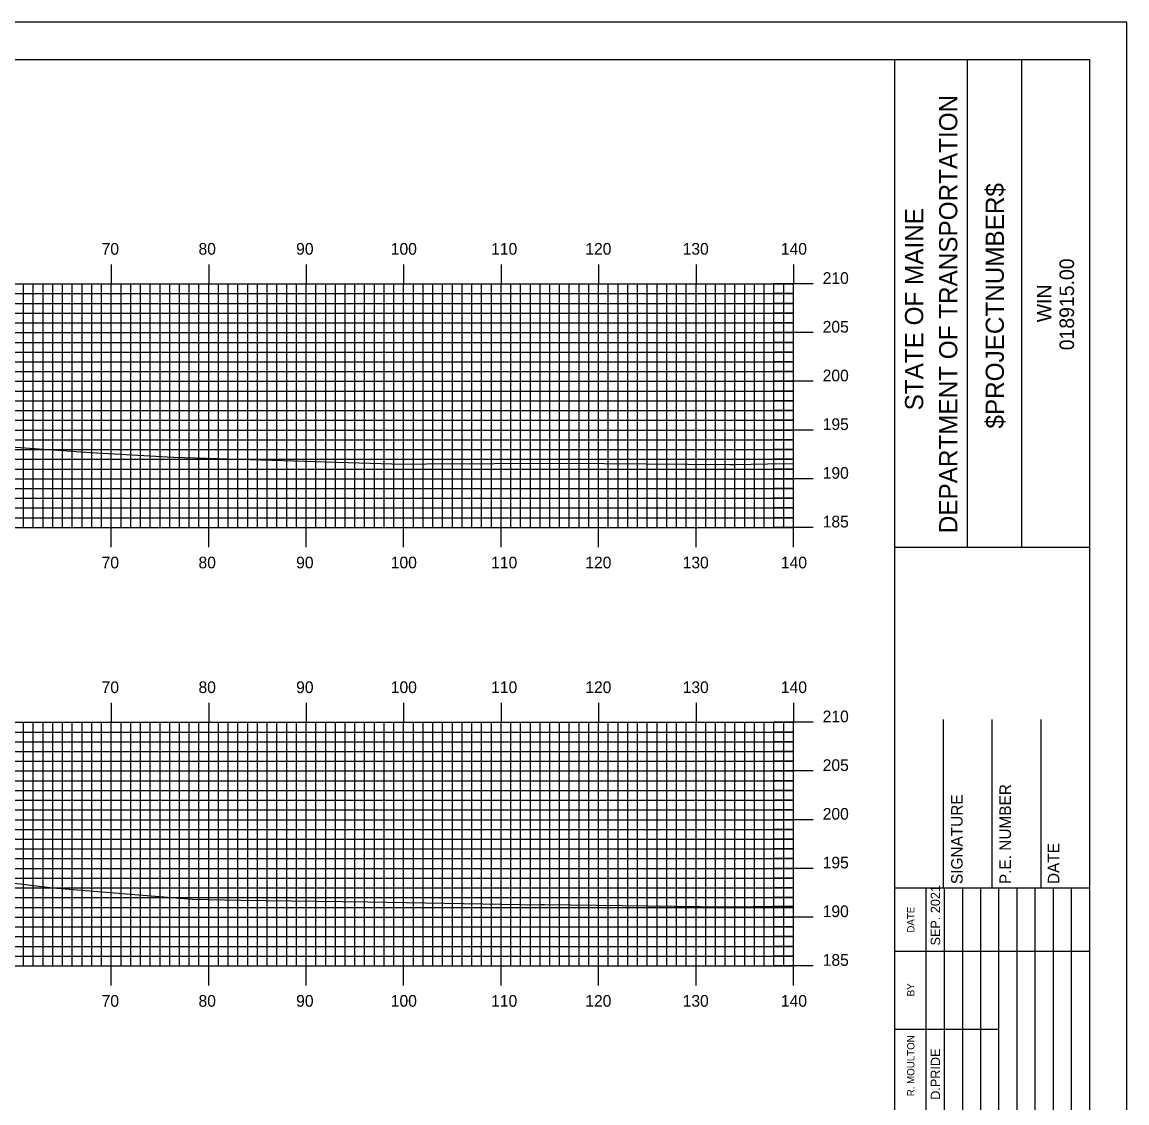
# Model space of a CAD drawing. Extents: x 1813735 to 1814078, y 442591 to 442811.
# Drawn here: x 1813961.3 to 1814074.7, y 442699.6 to 442810.5 of the extents above; entities that cross this region are included whole.
import ezdxf

# ---------------------------------------------------------------- set-up
doc = ezdxf.new("R2010")
doc.units = 0
for name, color, linetype in [('BORDER', 7, 'Continuous'), ('H_V ANNOTATION', 7, 'Continuous'), ('MAJOR', 7, 'Continuous'), ('MINOR', 7, 'Continuous'), ('PLOT BOUNDARY', 7, 'Continuous'), ('S_Roadway_Centerline', 7, 'Continuous')]:
    doc.layers.add(name, color=color, linetype=linetype)

msp = doc.modelspace()

# ---------------------------------------------------------------- linework, layer by layer
at = {"layer": 'BORDER'}
for p, q in [((1814050.88, 442596.67), (1814050.88, 442806.67)), ((1814058.34, 442756.66), (1814058.34, 442806.66)), ((1814063.93, 442756.66), (1814063.93, 442806.66)), ((1814050.88, 442756.65), (1814070.88, 442756.65)), ((1814055.88, 442721.67), (1814055.88, 442738.97)), ((1814060.88, 442721.67), (1814060.88, 442738.97)), ((1814065.88, 442721.67), (1814065.88, 442738.97)), ((1814050.88, 442721.67), (1814070.88, 442721.67))]:
    msp.add_line(p, q, dxfattribs=at)
msp.add_lwpolyline([(1813750.88, 442596.67), (1814070.88, 442596.67), (1814070.88, 442806.67), (1813750.88, 442806.67)], close=True, dxfattribs=at)
for points in [[(1814054.11, 442715.17), (1814054.11, 442721.67)], [(1814055.98, 442686.68), (1814055.98, 442721.67)], [(1814057.84, 442721.67), (1814057.84, 442686.68)], [(1814059.7, 442686.68), (1814059.7, 442721.67)], [(1814061.57, 442686.68), (1814061.57, 442721.67)], [(1814063.43, 442686.68), (1814063.43, 442721.67)], [(1814065.29, 442686.68), (1814065.29, 442721.67)], [(1814067.16, 442686.68), (1814067.16, 442721.67)], [(1814069.02, 442686.68), (1814069.02, 442721.67)], [(1814054.11, 442686.68), (1814054.11, 442720.26)], [(1814050.88, 442715.17), (1814070.88, 442715.17)], [(1814050.88, 442707.17), (1814054.11, 442707.17)], [(1814054.11, 442707.17), (1814061.56, 442707.17)]]:
    msp.add_lwpolyline(points, dxfattribs=at)
at = {"layer": 'MAJOR'}
for p, q in [((1813970.48, 442785.67), (1813970.48, 442783.67)), ((1813980.48, 442785.67), (1813980.48, 442783.67)), ((1813990.48, 442785.67), (1813990.48, 442783.67)), ((1814000.48, 442785.67), (1814000.48, 442783.67)), ((1814010.48, 442785.67), (1814010.48, 442783.67)), ((1814020.48, 442785.67), (1814020.48, 442783.67)), ((1814030.48, 442785.67), (1814030.48, 442783.67)), ((1814040.48, 442785.67), (1814040.48, 442783.67)), ((1813760.48, 442783.67), (1814040.48, 442783.67)), ((1813760.48, 442783.67), (1814040.48, 442783.67)), ((1813970.48, 442758.67), (1813970.48, 442783.67)), ((1813980.48, 442758.67), (1813980.48, 442783.67)), ((1813990.48, 442758.67), (1813990.48, 442783.67)), ((1814000.48, 442758.67), (1814000.48, 442783.67)), ((1814010.48, 442758.67), (1814010.48, 442783.67)), ((1814020.48, 442758.67), (1814020.48, 442783.67)), ((1814030.48, 442758.67), (1814030.48, 442783.67)), ((1814042.49, 442783.67), (1814038.48, 442783.67)), ((1814040.48, 442758.67), (1814040.48, 442783.67)), ((1814040.48, 442758.67), (1814040.48, 442783.67)), ((1813760.48, 442778.67), (1814040.48, 442778.67)), ((1814042.49, 442778.67), (1814038.48, 442778.67)), ((1813760.48, 442773.67), (1814040.48, 442773.67)), ((1814042.49, 442773.67), (1814038.48, 442773.67)), ((1813760.48, 442768.67), (1814040.48, 442768.67)), ((1814042.49, 442768.67), (1814038.48, 442768.67)), ((1813760.48, 442763.67), (1814040.48, 442763.67)), ((1814042.49, 442763.67), (1814038.48, 442763.67)), ((1813760.48, 442758.67), (1814040.48, 442758.67)), ((1813760.48, 442758.67), (1814040.48, 442758.67)), ((1813970.48, 442756.66), (1813970.48, 442758.67)), ((1813980.48, 442756.66), (1813980.48, 442758.67)), ((1813990.48, 442756.66), (1813990.48, 442758.67)), ((1814000.48, 442756.66), (1814000.48, 442758.67)), ((1814010.48, 442756.66), (1814010.48, 442758.67)), ((1814020.48, 442756.66), (1814020.48, 442758.67)), ((1814030.48, 442756.66), (1814030.48, 442758.67)), ((1814042.49, 442758.67), (1814038.48, 442758.67)), ((1814040.48, 442756.66), (1814040.48, 442758.67)), ((1813970.48, 442740.67), (1813970.48, 442738.67)), ((1813980.48, 442740.67), (1813980.48, 442738.67)), ((1813990.48, 442740.67), (1813990.48, 442738.67)), ((1814000.48, 442740.67), (1814000.48, 442738.67)), ((1814010.48, 442740.67), (1814010.48, 442738.67)), ((1814020.48, 442740.67), (1814020.48, 442738.67)), ((1814030.48, 442740.67), (1814030.48, 442738.67)), ((1814040.48, 442740.67), (1814040.48, 442738.67)), ((1813760.48, 442738.67), (1814040.48, 442738.67)), ((1813760.48, 442738.67), (1814040.48, 442738.67)), ((1813970.48, 442713.67), (1813970.48, 442738.67)), ((1813980.48, 442713.67), (1813980.48, 442738.67)), ((1813990.48, 442713.67), (1813990.48, 442738.67)), ((1814000.48, 442713.67), (1814000.48, 442738.67)), ((1814010.48, 442713.67), (1814010.48, 442738.67)), ((1814020.48, 442713.67), (1814020.48, 442738.67)), ((1814030.48, 442713.67), (1814030.48, 442738.67)), ((1814042.49, 442738.67), (1814038.48, 442738.67)), ((1814040.48, 442713.67), (1814040.48, 442738.67)), ((1814040.48, 442713.67), (1814040.48, 442738.67)), ((1813760.48, 442733.67), (1814040.48, 442733.67)), ((1814042.49, 442733.67), (1814038.48, 442733.67)), ((1813760.48, 442728.67), (1814040.48, 442728.67)), ((1814042.49, 442728.67), (1814038.48, 442728.67)), ((1813760.48, 442723.67), (1814040.48, 442723.67)), ((1814042.49, 442723.67), (1814038.48, 442723.67)), ((1813760.48, 442718.67), (1814040.48, 442718.67)), ((1814042.49, 442718.67), (1814038.48, 442718.67)), ((1813760.48, 442713.67), (1814040.48, 442713.67)), ((1813760.48, 442713.67), (1814040.48, 442713.67)), ((1813970.48, 442711.66), (1813970.48, 442713.67)), ((1813980.48, 442711.66), (1813980.48, 442713.67)), ((1813990.48, 442711.66), (1813990.48, 442713.67)), ((1814000.48, 442711.66), (1814000.48, 442713.67)), ((1814010.48, 442711.66), (1814010.48, 442713.67)), ((1814020.48, 442711.66), (1814020.48, 442713.67)), ((1814030.48, 442711.66), (1814030.48, 442713.67)), ((1814042.49, 442713.67), (1814038.48, 442713.67)), ((1814040.48, 442711.66), (1814040.48, 442713.67))]:
    msp.add_line(p, q, dxfattribs=at)
at = {"layer": 'MINOR'}
for p, q in [((1813961.48, 442758.67), (1813961.48, 442783.67)), ((1813962.48, 442758.67), (1813962.48, 442783.67)), ((1813963.48, 442758.67), (1813963.48, 442783.67)), ((1813964.48, 442758.67), (1813964.48, 442783.67)), ((1813965.48, 442758.67), (1813965.48, 442783.67)), ((1813966.48, 442758.67), (1813966.48, 442783.67)), ((1813967.48, 442758.67), (1813967.48, 442783.67)), ((1813968.48, 442758.67), (1813968.48, 442783.67)), ((1813969.48, 442758.67), (1813969.48, 442783.67)), ((1813971.48, 442758.67), (1813971.48, 442783.67)), ((1813972.48, 442758.67), (1813972.48, 442783.67)), ((1813973.48, 442758.67), (1813973.48, 442783.67)), ((1813974.48, 442758.67), (1813974.48, 442783.67)), ((1813975.48, 442758.67), (1813975.48, 442783.67)), ((1813976.48, 442758.67), (1813976.48, 442783.67)), ((1813977.48, 442758.67), (1813977.48, 442783.67)), ((1813978.48, 442758.67), (1813978.48, 442783.67)), ((1813979.48, 442758.67), (1813979.48, 442783.67)), ((1813981.48, 442758.67), (1813981.48, 442783.67)), ((1813982.48, 442758.67), (1813982.48, 442783.67)), ((1813983.48, 442758.67), (1813983.48, 442783.67)), ((1813984.48, 442758.67), (1813984.48, 442783.67)), ((1813985.48, 442758.67), (1813985.48, 442783.67)), ((1813986.48, 442758.67), (1813986.48, 442783.67)), ((1813987.48, 442758.67), (1813987.48, 442783.67)), ((1813988.48, 442758.67), (1813988.48, 442783.67)), ((1813989.48, 442758.67), (1813989.48, 442783.67)), ((1813991.48, 442758.67), (1813991.48, 442783.67)), ((1813992.48, 442758.67), (1813992.48, 442783.67)), ((1813993.48, 442758.67), (1813993.48, 442783.67)), ((1813994.48, 442758.67), (1813994.48, 442783.67)), ((1813995.48, 442758.67), (1813995.48, 442783.67)), ((1813996.48, 442758.67), (1813996.48, 442783.67)), ((1813997.48, 442758.67), (1813997.48, 442783.67)), ((1813998.48, 442758.67), (1813998.48, 442783.67)), ((1813999.48, 442758.67), (1813999.48, 442783.67)), ((1814001.48, 442758.67), (1814001.48, 442783.67)), ((1814002.48, 442758.67), (1814002.48, 442783.67)), ((1814003.48, 442758.67), (1814003.48, 442783.67)), ((1814004.48, 442758.67), (1814004.48, 442783.67)), ((1814005.48, 442758.67), (1814005.48, 442783.67)), ((1814006.48, 442758.67), (1814006.48, 442783.67)), ((1814007.48, 442758.67), (1814007.48, 442783.67)), ((1814008.48, 442758.67), (1814008.48, 442783.67)), ((1814009.48, 442758.67), (1814009.48, 442783.67)), ((1814011.48, 442758.67), (1814011.48, 442783.67)), ((1814012.48, 442758.67), (1814012.48, 442783.67)), ((1814013.48, 442758.67), (1814013.48, 442783.67)), ((1814014.48, 442758.67), (1814014.48, 442783.67)), ((1814015.48, 442758.67), (1814015.48, 442783.67)), ((1814016.48, 442758.67), (1814016.48, 442783.67)), ((1814017.48, 442758.67), (1814017.48, 442783.67)), ((1814018.48, 442758.67), (1814018.48, 442783.67)), ((1814019.48, 442758.67), (1814019.48, 442783.67)), ((1814021.48, 442758.67), (1814021.48, 442783.67)), ((1814022.48, 442758.67), (1814022.48, 442783.67)), ((1814023.48, 442758.67), (1814023.48, 442783.67)), ((1814024.48, 442758.67), (1814024.48, 442783.67)), ((1814025.48, 442758.67), (1814025.48, 442783.67)), ((1814026.48, 442758.67), (1814026.48, 442783.67)), ((1814027.48, 442758.67), (1814027.48, 442783.67)), ((1814028.48, 442758.67), (1814028.48, 442783.67)), ((1814029.48, 442758.67), (1814029.48, 442783.67)), ((1814031.48, 442758.67), (1814031.48, 442783.67)), ((1814032.48, 442758.67), (1814032.48, 442783.67)), ((1814033.48, 442758.67), (1814033.48, 442783.67)), ((1814034.48, 442758.67), (1814034.48, 442783.67)), ((1814035.48, 442758.67), (1814035.48, 442783.67)), ((1814036.48, 442758.67), (1814036.48, 442783.67)), ((1814037.48, 442758.67), (1814037.48, 442783.67)), ((1814038.48, 442758.67), (1814038.48, 442783.67)), ((1814039.48, 442758.67), (1814039.48, 442783.67)), ((1813760.48, 442782.67), (1814040.48, 442782.67)), ((1814040.48, 442782.67), (1814038.48, 442782.67)), ((1813760.48, 442781.67), (1814040.48, 442781.67)), ((1813760.48, 442780.67), (1814040.48, 442780.67)), ((1814040.48, 442781.67), (1814038.48, 442781.67)), ((1814040.48, 442780.67), (1814038.48, 442780.67)), ((1813760.48, 442779.67), (1814040.48, 442779.67)), ((1814040.48, 442779.67), (1814038.48, 442779.67)), ((1813760.48, 442777.67), (1814040.48, 442777.67)), ((1814040.48, 442777.67), (1814038.48, 442777.67)), ((1813760.48, 442776.67), (1814040.48, 442776.67)), ((1814040.48, 442776.67), (1814038.48, 442776.67)), ((1813760.48, 442775.67), (1814040.48, 442775.67)), ((1814040.48, 442775.67), (1814038.48, 442775.67)), ((1813760.48, 442774.67), (1814040.48, 442774.67)), ((1814040.48, 442774.67), (1814038.48, 442774.67)), ((1813760.48, 442772.67), (1814040.48, 442772.67)), ((1814040.48, 442772.67), (1814038.48, 442772.67)), ((1813760.48, 442771.67), (1814040.48, 442771.67)), ((1814040.48, 442771.67), (1814038.48, 442771.67)), ((1813760.48, 442770.67), (1814040.48, 442770.67)), ((1814040.48, 442770.67), (1814038.48, 442770.67)), ((1813760.48, 442769.67), (1814040.48, 442769.67)), ((1814040.48, 442769.67), (1814038.48, 442769.67)), ((1813760.48, 442767.67), (1814040.48, 442767.67)), ((1814040.48, 442767.67), (1814038.48, 442767.67)), ((1813760.48, 442766.67), (1814040.48, 442766.67)), ((1814040.48, 442766.67), (1814038.48, 442766.67)), ((1813760.48, 442765.67), (1814040.48, 442765.67)), ((1814040.48, 442765.67), (1814038.48, 442765.67)), ((1813760.48, 442764.67), (1814040.48, 442764.67)), ((1814040.48, 442764.67), (1814038.48, 442764.67)), ((1813760.48, 442762.67), (1814040.48, 442762.67)), ((1814040.48, 442762.67), (1814038.48, 442762.67)), ((1813760.48, 442761.67), (1814040.48, 442761.67)), ((1814040.48, 442761.67), (1814038.48, 442761.67)), ((1813760.48, 442760.67), (1814040.48, 442760.67)), ((1814040.48, 442760.67), (1814038.48, 442760.67)), ((1813760.48, 442759.67), (1814040.48, 442759.67)), ((1814040.48, 442759.67), (1814038.48, 442759.67)), ((1813961.48, 442713.67), (1813961.48, 442738.67)), ((1813962.48, 442713.67), (1813962.48, 442738.67)), ((1813963.48, 442713.67), (1813963.48, 442738.67)), ((1813964.48, 442713.67), (1813964.48, 442738.67)), ((1813965.48, 442713.67), (1813965.48, 442738.67)), ((1813966.48, 442713.67), (1813966.48, 442738.67)), ((1813967.48, 442713.67), (1813967.48, 442738.67)), ((1813968.48, 442713.67), (1813968.48, 442738.67)), ((1813969.48, 442713.67), (1813969.48, 442738.67)), ((1813971.48, 442713.67), (1813971.48, 442738.67)), ((1813972.48, 442713.67), (1813972.48, 442738.67)), ((1813973.48, 442713.67), (1813973.48, 442738.67)), ((1813974.48, 442713.67), (1813974.48, 442738.67)), ((1813975.48, 442713.67), (1813975.48, 442738.67)), ((1813976.48, 442713.67), (1813976.48, 442738.67)), ((1813977.48, 442713.67), (1813977.48, 442738.67)), ((1813978.48, 442713.67), (1813978.48, 442738.67)), ((1813979.48, 442713.67), (1813979.48, 442738.67)), ((1813981.48, 442713.67), (1813981.48, 442738.67)), ((1813982.48, 442713.67), (1813982.48, 442738.67)), ((1813983.48, 442713.67), (1813983.48, 442738.67)), ((1813984.48, 442713.67), (1813984.48, 442738.67)), ((1813985.48, 442713.67), (1813985.48, 442738.67)), ((1813986.48, 442713.67), (1813986.48, 442738.67)), ((1813987.48, 442713.67), (1813987.48, 442738.67)), ((1813988.48, 442713.67), (1813988.48, 442738.67)), ((1813989.48, 442713.67), (1813989.48, 442738.67)), ((1813991.48, 442713.67), (1813991.48, 442738.67)), ((1813992.48, 442713.67), (1813992.48, 442738.67)), ((1813993.48, 442713.67), (1813993.48, 442738.67)), ((1813994.48, 442713.67), (1813994.48, 442738.67)), ((1813995.48, 442713.67), (1813995.48, 442738.67)), ((1813996.48, 442713.67), (1813996.48, 442738.67)), ((1813997.48, 442713.67), (1813997.48, 442738.67)), ((1813998.48, 442713.67), (1813998.48, 442738.67)), ((1813999.48, 442713.67), (1813999.48, 442738.67)), ((1814001.48, 442713.67), (1814001.48, 442738.67)), ((1814002.48, 442713.67), (1814002.48, 442738.67)), ((1814003.48, 442713.67), (1814003.48, 442738.67)), ((1814004.48, 442713.67), (1814004.48, 442738.67)), ((1814005.48, 442713.67), (1814005.48, 442738.67)), ((1814006.48, 442713.67), (1814006.48, 442738.67)), ((1814007.48, 442713.67), (1814007.48, 442738.67)), ((1814008.48, 442713.67), (1814008.48, 442738.67)), ((1814009.48, 442713.67), (1814009.48, 442738.67)), ((1814011.48, 442713.67), (1814011.48, 442738.67)), ((1814012.48, 442713.67), (1814012.48, 442738.67)), ((1814013.48, 442713.67), (1814013.48, 442738.67)), ((1814014.48, 442713.67), (1814014.48, 442738.67)), ((1814015.48, 442713.67), (1814015.48, 442738.67)), ((1814016.48, 442713.67), (1814016.48, 442738.67)), ((1814017.48, 442713.67), (1814017.48, 442738.67)), ((1814018.48, 442713.67), (1814018.48, 442738.67)), ((1814019.48, 442713.67), (1814019.48, 442738.67)), ((1814021.48, 442713.67), (1814021.48, 442738.67)), ((1814022.48, 442713.67), (1814022.48, 442738.67)), ((1814023.48, 442713.67), (1814023.48, 442738.67)), ((1814024.48, 442713.67), (1814024.48, 442738.67)), ((1814025.48, 442713.67), (1814025.48, 442738.67)), ((1814026.48, 442713.67), (1814026.48, 442738.67)), ((1814027.48, 442713.67), (1814027.48, 442738.67)), ((1814028.48, 442713.67), (1814028.48, 442738.67)), ((1814029.48, 442713.67), (1814029.48, 442738.67)), ((1814031.48, 442713.67), (1814031.48, 442738.67)), ((1814032.48, 442713.67), (1814032.48, 442738.67)), ((1814033.48, 442713.67), (1814033.48, 442738.67)), ((1814034.48, 442713.67), (1814034.48, 442738.67)), ((1814035.48, 442713.67), (1814035.48, 442738.67)), ((1814036.48, 442713.67), (1814036.48, 442738.67)), ((1814037.48, 442713.67), (1814037.48, 442738.67)), ((1814038.48, 442713.67), (1814038.48, 442738.67)), ((1814039.48, 442713.67), (1814039.48, 442738.67)), ((1813760.48, 442737.67), (1814040.48, 442737.67)), ((1814040.48, 442737.67), (1814038.48, 442737.67)), ((1813760.48, 442736.67), (1814040.48, 442736.67)), ((1814040.48, 442736.67), (1814038.48, 442736.67)), ((1813760.48, 442735.67), (1814040.48, 442735.67)), ((1814040.48, 442735.67), (1814038.48, 442735.67)), ((1813760.48, 442734.67), (1814040.48, 442734.67)), ((1814040.48, 442734.67), (1814038.48, 442734.67)), ((1813760.48, 442732.67), (1814040.48, 442732.67)), ((1814040.48, 442732.67), (1814038.48, 442732.67)), ((1813760.48, 442731.67), (1814040.48, 442731.67)), ((1814040.48, 442731.67), (1814038.48, 442731.67)), ((1813760.48, 442730.67), (1814040.48, 442730.67)), ((1813760.48, 442729.67), (1814040.48, 442729.67)), ((1814040.48, 442730.67), (1814038.48, 442730.67)), ((1814040.48, 442729.67), (1814038.48, 442729.67)), ((1813760.48, 442727.67), (1814040.48, 442727.67)), ((1814040.48, 442727.67), (1814038.48, 442727.67)), ((1813760.48, 442726.67), (1814040.48, 442726.67)), ((1814040.48, 442726.67), (1814038.48, 442726.67)), ((1813760.48, 442725.67), (1814040.48, 442725.67)), ((1814040.48, 442725.67), (1814038.48, 442725.67)), ((1813760.48, 442724.67), (1814040.48, 442724.67)), ((1814040.48, 442724.67), (1814038.48, 442724.67)), ((1813760.48, 442722.67), (1814040.48, 442722.67)), ((1813760.48, 442721.67), (1814040.48, 442721.67)), ((1814040.48, 442722.67), (1814038.48, 442722.67)), ((1814040.48, 442721.67), (1814038.48, 442721.67)), ((1813760.48, 442720.67), (1814040.48, 442720.67)), ((1814040.48, 442720.67), (1814038.48, 442720.67)), ((1813760.48, 442719.67), (1814040.48, 442719.67)), ((1814040.48, 442719.67), (1814038.48, 442719.67)), ((1813760.48, 442717.67), (1814040.48, 442717.67)), ((1814040.48, 442717.67), (1814038.48, 442717.67)), ((1813760.48, 442716.67), (1814040.48, 442716.67)), ((1814040.48, 442716.67), (1814038.48, 442716.67)), ((1813760.48, 442715.67), (1814040.48, 442715.67)), ((1814040.48, 442715.67), (1814038.48, 442715.67)), ((1813760.48, 442714.67), (1814040.48, 442714.67)), ((1814040.48, 442714.67), (1814038.48, 442714.67))]:
    msp.add_line(p, q, dxfattribs=at)
at = {"layer": 'PLOT BOUNDARY'}
msp.add_lwpolyline([(1813734.69, 442590.55), (1814074.69, 442590.55), (1814074.69, 442810.55), (1813734.69, 442810.55)], close=True, dxfattribs=at)
at = {"layer": 'S_Roadway_Centerline'}
for points in [[(1813956.33, 442767.23), (1813968.35, 442766.36), (1813976.86, 442765.89), (1814000.4, 442765.15), (1814002.84, 442765.21), (1814016.74, 442765.27), (1814033.95, 442765.14), (1814034.22, 442765.14), (1814034.45, 442765.14), (1814037.8, 442765.2), (1814040.48, 442765.25)], [(1813960.29, 442722.2), (1813964.48, 442721.67), (1813978.77, 442720.52), (1813983.75, 442720.42), (1813996.82, 442720.24), (1814010.55, 442720.01), (1814014.2, 442719.94), (1814014.54, 442719.96), (1814014.94, 442719.95), (1814033.59, 442719.72), (1814034.28, 442719.72), (1814040.48, 442719.82)]]:
    msp.add_lwpolyline(points, dxfattribs=at)

# ---------------------------------------------------------------- texts
at = {"layer": 'BORDER'}
for s, height, p in [('DEPARTMENT OF TRANSPORTATION', 1.8635, (1814057.29, 442758.08)), ('$PROJECTNUMBER$', 1.8635, (1814062.07, 442768.82)), ('STATE OF MAINE', 1.8635, (1814053.79, 442770.69)), ('018915.00', 1.491, (1814069.27, 442776.86)), ('WIN', 1.491, (1814066.95, 442779.73)), ('P.E. NUMBER', 1.1811, (1814062.8, 442722.06)), ('SIGNATURE', 1.181, (1814057.84, 442722.06)), ('DATE', 1.181, (1814067.76, 442722.06)), ('SEP. 2021', 0.969, (1814055.53, 442715.76)), ('DATE', 0.743, (1814052.89, 442717.08)), ('BY', 0.743, (1814052.89, 442710.54)), ('R. MOULTON', 0.745, (1814052.89, 442700.28)), ('D.PRIDE', 0.969, (1814055.53, 442699.92))]:
    msp.add_text(s, height=height, rotation=90, dxfattribs=at).set_placement(p)
at = {"layer": 'H_V ANNOTATION'}
for s, p in [('70', (1813969.49, 442786.67)), ('80', (1813979.43, 442786.67)), ('90', (1813989.45, 442786.67)), ('100', (1813999.16, 442786.67)), ('110', (1814009.46, 442786.67)), ('120', (1814019.12, 442786.67)), ('130', (1814029.11, 442786.67)), ('140', (1814039.19, 442786.67)), ('210', (1814043.48, 442783.67)), ('205', (1814043.48, 442778.67)), ('200', (1814043.48, 442773.67)), ('195', (1814043.48, 442768.67)), ('190', (1814043.48, 442763.67)), ('185', (1814043.48, 442758.67)), ('70', (1813969.49, 442754.47)), ('80', (1813979.43, 442754.47)), ('90', (1813989.45, 442754.47)), ('100', (1813999.16, 442754.47)), ('110', (1814009.46, 442754.47)), ('120', (1814019.12, 442754.47)), ('130', (1814029.11, 442754.47)), ('140', (1814039.19, 442754.47)), ('70', (1813969.49, 442741.67)), ('80', (1813979.43, 442741.67)), ('90', (1813989.45, 442741.67)), ('100', (1813999.16, 442741.67)), ('110', (1814009.46, 442741.67)), ('120', (1814019.12, 442741.67)), ('130', (1814029.11, 442741.67)), ('140', (1814039.19, 442741.67)), ('210', (1814043.48, 442738.67)), ('205', (1814043.48, 442733.67)), ('200', (1814043.48, 442728.67)), ('195', (1814043.48, 442723.67)), ('190', (1814043.48, 442718.67)), ('185', (1814043.48, 442713.67)), ('70', (1813969.49, 442709.47)), ('80', (1813979.43, 442709.47)), ('90', (1813989.45, 442709.47)), ('100', (1813999.16, 442709.47)), ('110', (1814009.46, 442709.47)), ('120', (1814019.12, 442709.47)), ('130', (1814029.11, 442709.47)), ('140', (1814039.19, 442709.47))]:
    msp.add_text(s, height=1.2, dxfattribs=at).set_placement(p)

doc.saveas('drawing.dxf')
